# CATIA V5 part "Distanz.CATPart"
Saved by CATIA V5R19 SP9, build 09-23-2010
Part number: Distanz
Bounding box of the stored display mesh (mm): x -3.5 to 3.5, y -3.5 to 3.5, z 0 to 10
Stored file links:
  D:\Temporäre Sachen\Lasermodul KY-008 with mounting for adjustment\Distanz.CATPart
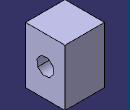
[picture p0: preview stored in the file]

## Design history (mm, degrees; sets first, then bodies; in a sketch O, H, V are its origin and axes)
Body1 (main body)
  Sketch1 on xy-plane, origin (0, 0, 0), H (1, 0, 0), V (0, 1, 0)
    line L1 (3.5, 3.5) -> (3.5, -3.5)
    line L2 (3.5, -3.5) -> (-3.5, -3.5)
    line L3 (-3.5, -3.5) -> (-3.5, 3.5)
    line L4 (-3.5, 3.5) -> (3.5, 3.5)
    distance L2 L4 = 7
    distance L1 L3 = 7
    vertical: L1 V, L3 V
    horizontal: L2 H, L4 H
    equidistance: L1 L3 O, L2 L4 O
  Pad1: profile Sketch1, direction (0, 0, 1), length 10
  Sketch2 on face of Pad1 from Sketch1.L3, origin (-3.5, 0, 0), H (0, -1, 0), V (0, 0, 1)
    point P1 (0, 5)
    distance P1 H = 5
    coincidence: P1 V
  Sketch3 on face of Pad1 from Sketch1.L3, origin (-3.5, 0, 5), H (0, 1, 0), V (0, 0, -1)
    point P1 (0, 0)
    reference projected point E1 (0, 0) from Sketch2.P1
    coincidence: E1 P1
  Hole1: placed by Sketch3, at (-3.5, 0, 5) direction (1, 0, 0), diameter 3.1, depth 10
